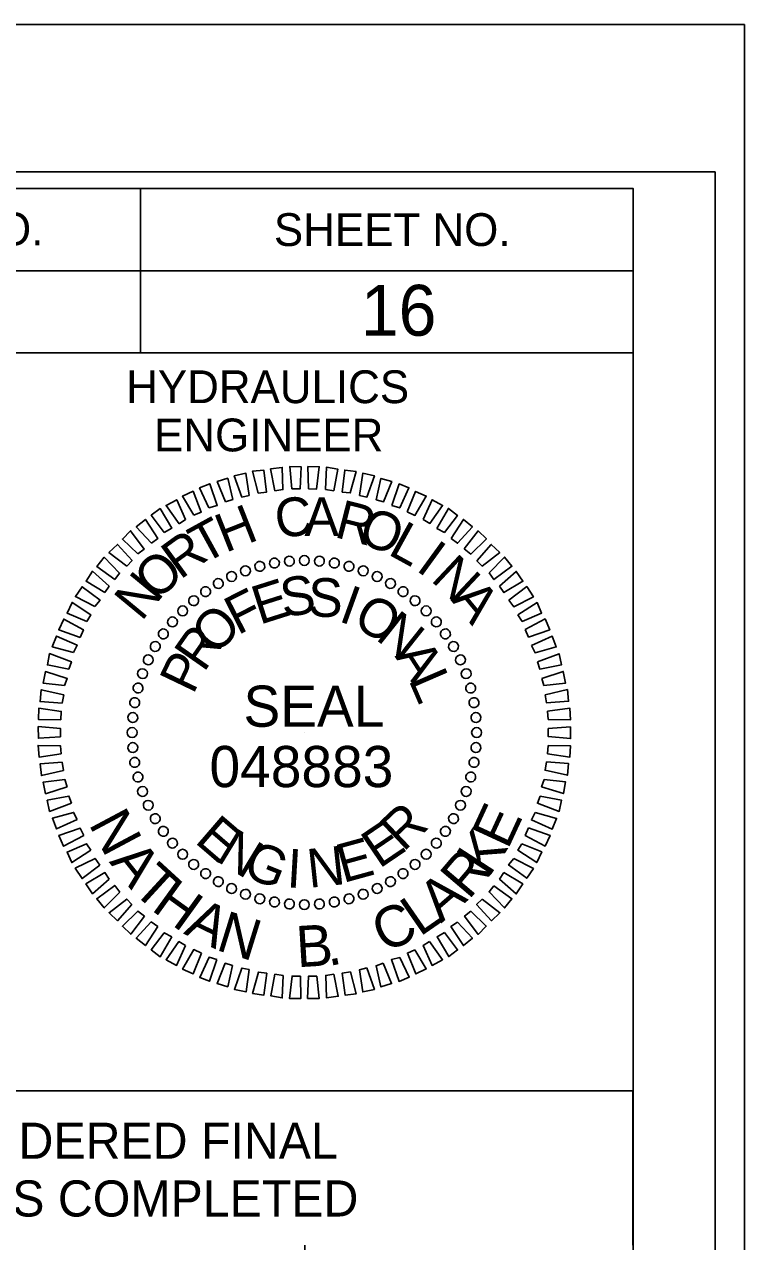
# Model space of a CAD drawing. Extents: x 1648123 to 1650776, y 802691 to 803791.
# Drawn here: x 1650436.6 to 1650546.3, y 803605.5 to 803791 of the extents above; entities that cross this region are included whole.
import ezdxf

# ---------------------------------------------------------------- set-up
doc = ezdxf.new("R2010")
doc.units = 0
for name, color, linetype in [('Default', 7, 'Continuous'), ('Old_Level_2', 7, 'Continuous'), ('Sheet Cutting Line CELL', 7, 'Continuous'), ('Sheet Data Field CELL', 7, 'Continuous'), ('Sheet Plot Border Inside CELL', 7, 'Continuous'), ('Sheet Plot Border Outside CELL', 7, 'Continuous'), ('Sheet Profile CELL', 7, 'Continuous'), ('Sheet Profile Grid Major CELL', 7, 'Continuous'), ('Sheet Sticker Exception Certification CELL', 7, 'Continuous')]:
    doc.layers.add(name, color=color, linetype=linetype)

msp = doc.modelspace()

# ---------------------------------------------------------------- linework, layer by layer
at = {"layer": 'Old_Level_2'}
for p, q in [((1650476.94, 803709.25), (1650476.94, 803709.25)), ((1650479.24, 803709.34), (1650479.24, 803709.34)), ((1650481.55, 803709.22), (1650481.55, 803709.22)), ((1650470.22, 803707.77), (1650470.22, 803707.77)), ((1650472.41, 803708.44), (1650472.41, 803708.44)), ((1650474.7, 803708.89), (1650474.7, 803708.89)), ((1650483.8, 803708.9), (1650483.8, 803708.9)), ((1650486.01, 803708.46), (1650486.01, 803708.46)), ((1650488.21, 803707.77), (1650488.21, 803707.77)), ((1650466.13, 803705.82), (1650466.13, 803705.82)), ((1650468.15, 803706.9), (1650468.15, 803706.9)), ((1650490.32, 803706.87), (1650490.32, 803706.87)), ((1650492.38, 803705.86), (1650492.38, 803705.86)), ((1650464.16, 803704.58), (1650464.16, 803704.58)), ((1650494.28, 803704.58), (1650494.28, 803704.58)), ((1650462.35, 803703.24), (1650462.35, 803703.24)), ((1650496.14, 803703.2), (1650496.14, 803703.2)), ((1650459.12, 803699.99), (1650459.12, 803699.99)), ((1650460.66, 803701.64), (1650460.66, 803701.64)), ((1650497.79, 803701.66), (1650497.79, 803701.66)), ((1650499.38, 803699.96), (1650499.38, 803699.96)), ((1650457.74, 803698.14), (1650457.74, 803698.14)), ((1650500.72, 803698.16), (1650500.72, 803698.16)), ((1650456.46, 803696.23), (1650456.46, 803696.23)), ((1650501.96, 803696.19), (1650501.96, 803696.19)), ((1650455.45, 803694.18), (1650455.45, 803694.18)), ((1650503.04, 803694.17), (1650503.04, 803694.17)), ((1650454.55, 803692.07), (1650454.55, 803692.07)), ((1650503.91, 803692.09), (1650503.91, 803692.09)), ((1650453.85, 803689.86), (1650453.85, 803689.86)), ((1650504.58, 803689.91), (1650504.58, 803689.91)), ((1650453.42, 803687.66), (1650453.42, 803687.66)), ((1650505.04, 803687.62), (1650505.04, 803687.62)), ((1650453.1, 803685.4), (1650453.1, 803685.4)), ((1650505.39, 803685.37), (1650505.39, 803685.37)), ((1650452.98, 803683.1), (1650452.98, 803683.1)), ((1650479.23, 803683.09), (1650479.23, 803683.09)), ((1650505.48, 803683.07), (1650505.48, 803683.07)), ((1650453.07, 803680.8), (1650453.07, 803680.8)), ((1650505.37, 803680.77), (1650505.37, 803680.77)), ((1650453.42, 803678.56), (1650453.42, 803678.56)), ((1650505.04, 803678.52), (1650505.04, 803678.52)), ((1650453.88, 803676.26), (1650453.88, 803676.26)), ((1650504.61, 803676.31), (1650504.61, 803676.31)), ((1650454.55, 803674.08), (1650454.55, 803674.08)), ((1650503.92, 803674.1), (1650503.92, 803674.1)), ((1650455.42, 803672), (1650455.42, 803672)), ((1650503.01, 803672), (1650503.01, 803672)), ((1650456.5, 803669.98), (1650456.5, 803669.98)), ((1650502, 803669.94), (1650502, 803669.94)), ((1650457.74, 803668.02), (1650457.74, 803668.02)), ((1650500.73, 803668.03), (1650500.73, 803668.03)), ((1650459.08, 803666.21), (1650459.08, 803666.21)), ((1650499.35, 803666.18), (1650499.35, 803666.18)), ((1650460.68, 803664.51), (1650460.68, 803664.51)), ((1650462.32, 803662.97), (1650462.32, 803662.97)), ((1650496.11, 803662.93), (1650496.11, 803662.93)), ((1650497.81, 803664.53), (1650497.81, 803664.53)), ((1650464.18, 803661.59), (1650464.18, 803661.59)), ((1650494.3, 803661.59), (1650494.3, 803661.59)), ((1650466.08, 803660.32), (1650466.08, 803660.32)), ((1650468.14, 803659.31), (1650468.14, 803659.31)), ((1650490.32, 803659.28), (1650490.32, 803659.28)), ((1650492.34, 803660.36), (1650492.34, 803660.36)), ((1650470.25, 803658.4), (1650470.25, 803658.4)), ((1650472.46, 803657.71), (1650472.46, 803657.71)), ((1650474.66, 803657.28), (1650474.66, 803657.28)), ((1650483.76, 803657.28), (1650483.76, 803657.28)), ((1650486.05, 803657.74), (1650486.05, 803657.74)), ((1650488.24, 803658.4), (1650488.24, 803658.4)), ((1650476.92, 803656.95), (1650476.92, 803656.95)), ((1650479.22, 803656.83), (1650479.22, 803656.83)), ((1650481.52, 803656.93), (1650481.52, 803656.93))]:
    msp.add_line(p, q, dxfattribs=at)
for points in [[(1650469.71, 803718.95), (1650468.56, 803722.23), (1650470.33, 803722.62), (1650470.81, 803719.23)], [(1650472.21, 803719.57), (1650471.32, 803722.9), (1650473.04, 803723.09), (1650473.47, 803719.75)], [(1650474.72, 803719.93), (1650474.08, 803723.26), (1650475.86, 803723.5), (1650475.97, 803720.11)], [(1650477.33, 803720.24), (1650477.01, 803723.63), (1650478.73, 803723.61), (1650478.58, 803720.21)], [(1650479.84, 803720.23), (1650479.78, 803723.63), (1650481.5, 803723.6), (1650481.09, 803720.2)], [(1650482.45, 803720.12), (1650482.6, 803723.52), (1650484.34, 803723.23), (1650483.71, 803719.93)], [(1650484.97, 803719.74), (1650485.38, 803723.1), (1650487.11, 803722.86), (1650486.23, 803719.61)], [(1650487.65, 803719.21), (1650488.11, 803722.62), (1650489.9, 803722.23), (1650488.75, 803718.97)], [(1650464.67, 803717.35), (1650463.26, 803720.36), (1650464.82, 803721.01), (1650465.97, 803717.68)], [(1650467.22, 803718.23), (1650465.96, 803721.34), (1650467.57, 803721.84), (1650468.31, 803718.61)], [(1650490.17, 803718.58), (1650490.9, 803721.83), (1650492.53, 803721.34), (1650491.27, 803718.23)], [(1650492.54, 803717.68), (1650493.68, 803720.99), (1650495.16, 803720.39), (1650493.75, 803717.33)], [(1650460.16, 803714.92), (1650458.18, 803717.71), (1650459.79, 803718.57), (1650461.15, 803715.56)], [(1650462.39, 803716.21), (1650460.66, 803719.11), (1650462.27, 803719.87), (1650463.53, 803716.7)], [(1650494.91, 803716.72), (1650496.16, 803719.83), (1650497.79, 803719.13), (1650496.07, 803716.17)], [(1650497.33, 803715.56), (1650498.69, 803718.57), (1650500.28, 803717.71), (1650498.34, 803714.95)], [(1650457.89, 803713.57), (1650455.9, 803716.2), (1650457.25, 803717.22), (1650459.02, 803714.22)], [(1650499.4, 803714.19), (1650501.17, 803717.25), (1650502.55, 803716.18), (1650500.56, 803713.58)], [(1650455.93, 803711.97), (1650453.63, 803714.44), (1650455.03, 803715.56), (1650456.91, 803712.66)], [(1650501.57, 803712.66), (1650503.45, 803715.57), (1650504.83, 803714.44), (1650502.57, 803711.94)], [(1650453.86, 803710.31), (1650451.52, 803712.57), (1650452.76, 803713.85), (1650454.84, 803711.06)], [(1650503.58, 803711.07), (1650505.68, 803713.83), (1650506.96, 803712.59), (1650504.59, 803710.3)], [(1650452.17, 803708.45), (1650449.47, 803710.55), (1650450.75, 803711.77), (1650452.99, 803709.3)], [(1650505.5, 803709.27), (1650507.7, 803711.77), (1650508.98, 803710.54), (1650506.3, 803708.45)], [(1650450.37, 803706.43), (1650447.62, 803708.42), (1650448.75, 803709.8), (1650451.09, 803707.38)], [(1650507.36, 803707.42), (1650509.72, 803709.82), (1650510.85, 803708.43), (1650508.11, 803706.39)], [(1650448.84, 803704.42), (1650445.99, 803706.14), (1650446.95, 803707.68), (1650449.5, 803705.42)], [(1650508.96, 803705.41), (1650511.49, 803707.65), (1650512.51, 803706.15), (1650509.61, 803704.43)], [(1650447.31, 803702.3), (1650444.35, 803703.81), (1650445.37, 803705.3), (1650448.13, 803703.25)], [(1650510.36, 803703.29), (1650513.1, 803705.33), (1650514.12, 803703.78), (1650511.11, 803702.26)], [(1650446.09, 803700.03), (1650443.09, 803701.28), (1650443.85, 803702.92), (1650446.7, 803701.03)], [(1650511.76, 803701.02), (1650514.66, 803702.9), (1650515.36, 803701.29), (1650512.41, 803700.03)], [(1650445.09, 803697.6), (1650441.83, 803698.75), (1650442.58, 803700.38), (1650445.59, 803698.76)], [(1650512.85, 803698.79), (1650515.9, 803700.41), (1650516.61, 803698.75), (1650513.39, 803697.65)], [(1650444.08, 803695.29), (1650440.83, 803696.17), (1650441.48, 803697.8), (1650444.64, 803696.39)], [(1650513.83, 803696.35), (1650516.99, 803697.76), (1650517.6, 803696.15), (1650514.37, 803695.26)], [(1650443.34, 803692.76), (1650440.09, 803693.39), (1650440.43, 803695.12), (1650443.74, 803693.87)], [(1650514.71, 803693.85), (1650518.03, 803695.11), (1650518.38, 803693.39), (1650515.09, 803692.76)], [(1650442.71, 803690.24), (1650439.46, 803690.6), (1650439.79, 803692.39), (1650443.11, 803691.35)], [(1650515.38, 803691.35), (1650518.66, 803692.4), (1650519, 803690.63), (1650515.71, 803690.26)], [(1650442.34, 803687.57), (1650438.99, 803687.82), (1650439.16, 803689.6), (1650442.58, 803688.83)], [(1650515.89, 803688.85), (1650519.28, 803689.64), (1650519.47, 803687.87), (1650516.13, 803687.6)], [(1650442.12, 803685.05), (1650438.72, 803685.1), (1650438.79, 803686.83), (1650442.2, 803686.31)], [(1650516.25, 803686.35), (1650519.64, 803686.82), (1650519.78, 803685.05), (1650516.38, 803685.09)], [(1650442.11, 803682.44), (1650438.72, 803682.22), (1650438.69, 803684), (1650442.09, 803683.69)], [(1650516.35, 803683.73), (1650519.75, 803683.95), (1650519.78, 803682.17), (1650516.37, 803682.48)], [(1650442.21, 803679.83), (1650438.82, 803679.35), (1650438.68, 803681.12), (1650442.08, 803681.08)], [(1650516.34, 803681.12), (1650519.74, 803681.07), (1650519.67, 803679.35), (1650516.26, 803679.86)], [(1650442.57, 803677.32), (1650439.18, 803676.53), (1650438.99, 803678.3), (1650442.34, 803678.57)], [(1650516.13, 803678.61), (1650519.48, 803678.35), (1650519.3, 803676.57), (1650515.89, 803677.35)], [(1650443.08, 803674.82), (1650439.81, 803673.77), (1650439.46, 803675.54), (1650442.75, 803675.91)], [(1650515.75, 803675.93), (1650519, 803675.57), (1650518.67, 803673.79), (1650515.36, 803674.83)], [(1650443.75, 803672.32), (1650440.43, 803671.06), (1650440.08, 803672.78), (1650443.37, 803673.41)], [(1650515.12, 803673.41), (1650518.37, 803672.79), (1650518.04, 803671.06), (1650514.72, 803672.31)], [(1650444.63, 803669.83), (1650441.47, 803668.41), (1650440.86, 803670.02), (1650444.09, 803670.92)], [(1650514.38, 803670.89), (1650517.64, 803670), (1650516.98, 803668.37), (1650513.82, 803669.78)], [(1650445.62, 803667.39), (1650442.56, 803665.76), (1650441.85, 803667.42), (1650445.07, 803668.53)], [(1650513.37, 803668.57), (1650516.64, 803667.42), (1650515.88, 803665.79), (1650512.87, 803667.41)], [(1650446.7, 803665.16), (1650443.81, 803663.28), (1650443.1, 803664.88), (1650446.06, 803666.14)], [(1650512.37, 803666.15), (1650515.37, 803664.89), (1650514.62, 803663.26), (1650511.76, 803665.14)], [(1650448.1, 803662.88), (1650445.37, 803660.84), (1650444.34, 803662.4), (1650447.35, 803663.91)], [(1650511.15, 803663.88), (1650514.11, 803662.36), (1650513.09, 803660.88), (1650510.33, 803662.92)], [(1650449.5, 803660.76), (1650446.97, 803658.52), (1650445.96, 803660.02), (1650448.85, 803661.74)], [(1650509.62, 803661.76), (1650512.48, 803660.03), (1650511.51, 803658.5), (1650508.96, 803660.75)], [(1650451.1, 803658.75), (1650448.74, 803656.35), (1650447.62, 803657.75), (1650450.35, 803659.78)], [(1650508.09, 803659.74), (1650510.84, 803657.75), (1650509.72, 803656.37), (1650507.37, 803658.79)], [(1650452.97, 803656.9), (1650450.76, 803654.4), (1650449.48, 803655.63), (1650452.17, 803657.72)], [(1650506.29, 803657.72), (1650509, 803655.63), (1650507.71, 803654.4), (1650505.47, 803656.87)], [(1650454.88, 803655.1), (1650452.78, 803652.35), (1650451.51, 803653.58), (1650453.87, 803655.87)], [(1650504.6, 803655.86), (1650506.94, 803653.6), (1650505.71, 803652.33), (1650503.62, 803655.12)], [(1650456.89, 803653.52), (1650455.01, 803650.61), (1650453.63, 803651.73), (1650455.89, 803654.23)], [(1650502.54, 803654.21), (1650504.83, 803651.74), (1650503.44, 803650.61), (1650501.56, 803653.51)], [(1650459.06, 803651.98), (1650457.29, 803648.92), (1650455.91, 803649.99), (1650457.9, 803652.59)], [(1650500.58, 803652.6), (1650502.56, 803649.97), (1650501.22, 803648.95), (1650499.44, 803651.96)], [(1650461.13, 803650.61), (1650459.77, 803647.6), (1650458.18, 803648.46), (1650460.12, 803651.22)], [(1650463.55, 803649.45), (1650462.3, 803646.34), (1650460.67, 803647.04), (1650462.39, 803650)], [(1650496.07, 803649.96), (1650497.8, 803647.06), (1650496.19, 803646.3), (1650494.93, 803649.47)], [(1650498.3, 803651.26), (1650500.28, 803648.47), (1650498.68, 803647.6), (1650497.32, 803650.61)], [(1650465.92, 803648.5), (1650464.78, 803645.18), (1650463.3, 803645.78), (1650464.72, 803648.84)], [(1650468.29, 803647.6), (1650467.57, 803644.34), (1650465.94, 803644.83), (1650467.19, 803647.94)], [(1650491.25, 803647.94), (1650492.5, 803644.83), (1650490.89, 803644.33), (1650490.15, 803647.56)], [(1650493.79, 803648.82), (1650495.2, 803645.82), (1650493.65, 803645.16), (1650492.49, 803648.49)], [(1650470.81, 803646.96), (1650470.35, 803643.55), (1650468.57, 803643.94), (1650469.71, 803647.2)], [(1650473.49, 803646.43), (1650473.08, 803643.08), (1650471.35, 803643.31), (1650472.23, 803646.57)], [(1650476.01, 803646.06), (1650475.86, 803642.65), (1650474.13, 803642.94), (1650474.75, 803646.24)], [(1650483.74, 803646.24), (1650484.38, 803642.91), (1650482.6, 803642.67), (1650482.49, 803646.07)], [(1650486.25, 803646.6), (1650487.14, 803643.27), (1650485.42, 803643.08), (1650485, 803646.42)], [(1650488.75, 803647.22), (1650489.9, 803643.95), (1650488.13, 803643.55), (1650487.65, 803646.94)], [(1650478.62, 803645.95), (1650478.68, 803642.55), (1650476.96, 803642.57), (1650477.37, 803645.98)], [(1650481.13, 803645.94), (1650481.46, 803642.54), (1650479.73, 803642.57), (1650479.88, 803645.97)]]:
    msp.add_lwpolyline(points, close=True, dxfattribs=at)
for centre, major_axis in [((1650472.44, 803708.42), (-0.195, 0.727)), ((1650474.68, 803708.92), (-0.131, 0.742)), ((1650476.95, 803709.21), (-0.066, 0.75)), ((1650479.23, 803709.31), (0, 0.753)), ((1650481.52, 803709.21), (0.066, 0.75)), ((1650483.79, 803708.92), (0.131, 0.742)), ((1650486.02, 803708.42), (0.195, 0.727)), ((1650468.15, 803706.86), (-0.318, 0.682)), ((1650470.26, 803707.73), (-0.258, 0.708)), ((1650488.2, 803707.73), (0.258, 0.708)), ((1650490.32, 803706.86), (0.318, 0.682)), ((1650466.12, 803705.8), (-0.376, 0.652)), ((1650492.35, 803705.8), (0.376, 0.652)), ((1650462.37, 803703.18), (-0.484, 0.577)), ((1650464.19, 803704.57), (-0.432, 0.617)), ((1650494.27, 803704.57), (0.432, 0.617)), ((1650496.09, 803703.18), (0.484, 0.577)), ((1650460.69, 803701.63), (-0.532, 0.532)), ((1650497.78, 803701.63), (0.532, 0.532)), ((1650459.14, 803699.95), (-0.577, 0.484)), ((1650499.32, 803699.95), (0.577, 0.484)), ((1650457.75, 803698.13), (-0.617, 0.432)), ((1650500.72, 803698.13), (0.617, 0.432)), ((1650456.52, 803696.2), (-0.652, 0.376)), ((1650501.95, 803696.2), (0.652, 0.376)), ((1650455.46, 803694.17), (-0.682, 0.318)), ((1650503, 803694.17), (0.682, 0.318)), ((1650454.59, 803692.06), (-0.708, 0.258)), ((1650503.88, 803692.06), (0.708, 0.258)), ((1650453.9, 803689.87), (-0.727, 0.195)), ((1650504.57, 803689.87), (0.727, 0.195)), ((1650453.4, 803687.64), (-0.742, 0.131)), ((1650505.06, 803687.64), (0.742, 0.131)), ((1650453.1, 803685.37), (-0.75, 0.066)), ((1650505.36, 803685.37), (0.75, 0.066)), ((1650453, 803683.09), (-0.753, 0)), ((1650505.46, 803683.09), (0.753, 0)), ((1650453.1, 803680.8), (-0.75, -0.066)), ((1650505.36, 803680.8), (0.75, -0.066)), ((1650453.4, 803678.53), (-0.742, -0.131)), ((1650505.06, 803678.53), (0.742, -0.131)), ((1650453.9, 803676.3), (-0.727, -0.195)), ((1650504.57, 803676.3), (0.727, -0.195)), ((1650454.59, 803674.12), (-0.708, -0.258)), ((1650503.88, 803674.12), (0.708, -0.258)), ((1650455.46, 803672), (-0.682, -0.318)), ((1650503, 803672), (0.682, -0.318)), ((1650456.52, 803669.97), (-0.652, -0.376)), ((1650501.95, 803669.97), (0.652, -0.376)), ((1650457.75, 803668.04), (-0.617, -0.432)), ((1650500.72, 803668.04), (0.617, -0.432)), ((1650459.14, 803666.23), (-0.577, -0.484)), ((1650499.32, 803666.23), (0.577, -0.484)), ((1650460.69, 803664.54), (-0.532, -0.532)), ((1650497.78, 803664.54), (0.532, -0.532)), ((1650462.37, 803662.99), (-0.484, -0.577)), ((1650496.09, 803662.99), (0.484, -0.577)), ((1650464.19, 803661.6), (-0.432, -0.617)), ((1650466.12, 803660.37), (-0.376, -0.652)), ((1650492.35, 803660.37), (0.376, -0.652)), ((1650494.27, 803661.6), (0.432, -0.617)), ((1650468.15, 803659.32), (-0.318, -0.682)), ((1650470.26, 803658.44), (-0.258, -0.708)), ((1650488.2, 803658.44), (0.258, -0.708)), ((1650490.32, 803659.32), (0.318, -0.682)), ((1650472.44, 803657.75), (-0.195, -0.727)), ((1650474.68, 803657.26), (-0.131, -0.742)), ((1650476.95, 803656.96), (-0.066, -0.75)), ((1650479.23, 803656.86), (0, -0.753)), ((1650481.52, 803656.96), (0.066, -0.75)), ((1650483.79, 803657.26), (0.131, -0.742)), ((1650486.02, 803657.75), (0.195, -0.727))]:
    msp.add_ellipse(centre, major_axis=major_axis, ratio=0.999708, dxfattribs=at)
at = {"layer": 'Sheet Cutting Line CELL'}
msp.add_line((1650546.28, 803791.02), (1648862.28, 803791.02), dxfattribs=at)
at = {"layer": 'Sheet Plot Border Inside CELL'}
msp.add_lwpolyline([(1648875.28, 802713.47), (1650541.78, 802713.47), (1650541.78, 803768.57), (1648875.28, 803768.57)], close=True, dxfattribs=at)
at = {"layer": 'Sheet Plot Border Outside CELL'}
msp.add_lwpolyline([(1648862.28, 802691.02), (1650546.28, 802691.02), (1650546.28, 803791.02), (1648862.28, 803791.02)], close=True, dxfattribs=at)
at = {"layer": 'Sheet Profile CELL'}
for p, q in [((1650454.28, 803765.97), (1650454.28, 803740.97)), ((1650329.23, 803753.47), (1650529.28, 803753.47))]:
    msp.add_line(p, q, dxfattribs=at)
for points in [[(1650529.28, 803766.02), (1649029.28, 803766.02), (1649029.28, 802716.02), (1650529.28, 802716.02)], [(1650329.23, 803766.02), (1650529.28, 803766.02), (1650529.28, 803740.97), (1650329.23, 803740.97)], [(1650429.28, 803740.97), (1650529.28, 803740.97), (1650529.28, 803628.47), (1650429.28, 803628.47)]]:
    msp.add_lwpolyline(points, close=True, dxfattribs=at)
at = {"layer": 'Sheet Profile Grid Major CELL'}
msp.add_lwpolyline([(1650479.28, 803604.97), (1650479.28, 803266.02), (1650529.28, 803266.02), (1650529.28, 803616.02)], dxfattribs=at)
at = {"layer": 'Sheet Sticker Exception Certification CELL'}
for p, q in [((1650329.23, 803628.47), (1650529.27, 803628.47)), ((1650329.23, 803628.47), (1650529.27, 803628.47)), ((1650529.27, 803628.46), (1650529.27, 803604.96)), ((1650529.27, 803628.46), (1650529.27, 803604.96))]:
    msp.add_line(p, q, dxfattribs=at)

# ---------------------------------------------------------------- texts
at = {"layer": 'Default'}
for s, rotation, p in [('E', 65.2198, (1650510.2, 803665.13)), ('N', 298.0773, (1650446.31, 803669.19)), ('K', 57.024, (1650507.33, 803660.9)), ('A', 308.6891, (1650449.42, 803663.36)), ('R', 49.6233, (1650504.25, 803657.47)), ('T', 317.4354, (1650452.76, 803659.05)), ('H', 324.1633, (1650455.75, 803656.11)), ('A', 40.877, (1650500.07, 803653.97)), ('L', 34.6689, (1650496.8, 803651.89)), ('A', 334.0411, (1650460.72, 803652.48)), ('N', 342.7874, (1650465.58, 803650.01)), ('C', 25.1886, (1650491.43, 803649.42)), ('B', 3.4911, (1650478.14, 803647.31)), ('.', 11.1059, (1650482.89, 803647.47))]:
    msp.add_text(s, height=6.27, rotation=rotation, dxfattribs=at).set_placement(p)
at = {"layer": 'Old_Level_2'}
for s, rotation, p in [('C', 7.2199, (1650475.11, 803712.67)), ('A', 0.0203, (1650479.23, 803713.05)), ('R', 345.6211, (1650483.63, 803712.92)), ('H', 21.6195, (1650467.2, 803710.44)), ('O', 338.4212, (1650487.14, 803712.2)), ('T', 28.8198, (1650463.83, 803708.65)), ('L', 331.2209, (1650491.78, 803710.34)), ('R', 36.0205, (1650460.31, 803706.29)), ('I', 324.0201, (1650496.06, 803707.91)), ('O', 43.2217, (1650456.76, 803702.99)), ('N', 316.8189, (1650498.33, 803706.33)), ('N', 50.4235, (1650454.41, 803699.91)), ('E', 17.6111, (1650472.41, 803699.49)), ('S', 8.2556, (1650476, 803700.65)), ('S', 358.9004, (1650479.76, 803700.77)), ('F', 26.967, (1650469.09, 803697.87)), ('I', 340.1896, (1650484.27, 803700.12)), ('O', 330.8335, (1650486.37, 803699.42)), ('A', 309.6172, (1650501.47, 803703.29)), ('O', 45.6812, (1650465.69, 803694.72)), ('N', 321.4766, (1650489.91, 803697.39)), ('R', 55.0397, (1650463.91, 803692.13)), ('P', 64.3989, (1650462.29, 803688.75)), ('A', 302.7603, (1650492.94, 803694.73)), ('L', 293.4009, (1650495.04, 803691.15)), ('E', 319.2769, (1650462.37, 803666.42)), ('R', 43.4814, (1650494.3, 803664.78)), ('N', 328.634, (1650465.56, 803663.65)), ('E', 34.1241, (1650490.63, 803662.26)), ('E', 15.4118, (1650485.12, 803660.13)), ('G', 337.9902, (1650469.57, 803661.37)), ('I', 356.7012, (1650476.45, 803659.5)), ('N', 6.0564, (1650479.96, 803659.41))]:
    msp.add_text(s, height=5.9, rotation=rotation, dxfattribs=at).set_placement(p)
for s, height, p in [('SEAL', 6.273, (1650469.96, 803683.97)), ('048883', 6.275, (1650464.78, 803674.77))]:
    msp.add_text(s, height=height, dxfattribs=at).set_placement(p)
at = {"layer": 'Sheet Data Field CELL'}
msp.add_text('16', height=7.75, dxfattribs=at).set_placement((1650487.82, 803743.57))
at = {"layer": 'Sheet Profile CELL'}
for s, height, p in [('PROJECT REFERENCE NO.', 5.0001, (1650351.44, 803757.34)), ('SHEET NO.', 5, (1650474.59, 803757.24)), ('HYDRAULICS', 5, (1650452.09, 803733.29)), ('ENGINEER', 5, (1650456.34, 803725.94))]:
    msp.add_text(s, height=height, dxfattribs=at).set_placement(p)
at = {"layer": 'Sheet Sticker Exception Certification CELL'}
for s, p in [('DOCUMENT NOT CONSIDERED FINAL', (1650350.3, 803618.13)), ('DOCUMENT NOT CONSIDERED FINAL', (1650350.3, 803618.13)), ('UNLESS ALL SIGNATURES COMPLETED', (1650345.23, 803609.33)), ('UNLESS ALL SIGNATURES COMPLETED', (1650345.23, 803609.33))]:
    msp.add_text(s, height=5.5, dxfattribs=at).set_placement(p)

doc.saveas('drawing.dxf')
